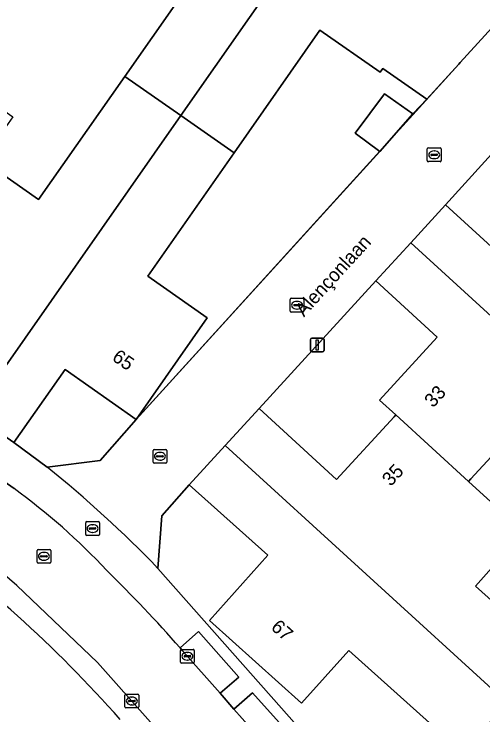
# Model space of a CAD drawing. Extents: x 158472 to 159562, y 388525 to 389606.
# Drawn here: x 158728.1 to 158762.2, y 389083.9 to 389134.9 of the extents above; entities that cross this region are included whole.
import ezdxf

# ---------------------------------------------------------------- set-up
doc = ezdxf.new("R2010")
doc.units = 0
for name, color, linetype in [('IMGEO_Brandkraan', 7, 'Continuous'), ('IMGEO_Erf', 7, 'Continuous'), ('IMGEO_Kolk', 7, 'Continuous'), ('IMGEO_Lichtmast', 7, 'Continuous'), ('IMGEO_Muur', 7, 'Continuous'), ('IMGEO_Openbare_ruimte_label', 7, 'Continuous'), ('IMGEO_Pand', 7, 'Continuous'), ('IMGEO_Pand_nummerreeks', 7, 'Continuous'), ('IMGEO_Parkeervlak_open', 7, 'Continuous'), ('IMGEO_Rijbaan_lokaal_open', 7, 'Continuous'), ('IMGEO_Rioolput', 7, 'Continuous'), ('IMGEO_Voetpad_open', 7, 'Continuous')]:
    doc.layers.add(name, color=color, linetype=linetype)

msp = doc.modelspace()

# ---------------------------------------------------------------- linework, layer by layer
at = {"layer": 'IMGEO_Brandkraan'}
for p, q in [((158733.348, 389097.923), (158734.2, 389097.923)), ((158733.273, 389096.997), (158733.273, 389097.849)), ((158733.532, 389097.417), (158733.532, 389097.429)), ((158733.575, 389097.466), (158733.973, 389097.466)), ((158733.761, 389097.703), (158733.786, 389097.703)), ((158734.016, 389097.429), (158734.016, 389097.417)), ((158734.274, 389097.849), (158734.274, 389096.997)), ((158734.2, 389096.923), (158733.348, 389096.923)), ((158733.97, 389097.38), (158733.572, 389097.38)), ((158733.784, 389097.143), (158733.759, 389097.143))]:
    msp.add_line(p, q, dxfattribs=at)
for points in [[(158733.348, 389097.923), (158734.2, 389097.923)], [(158733.273, 389096.997), (158733.273, 389097.849)], [(158734.274, 389097.849), (158734.274, 389096.997)], [(158734.2, 389096.923), (158733.348, 389096.923)]]:
    msp.add_lwpolyline(points, dxfattribs=at)
for centre, radius, start, end in [((158733.35, 389097.847), 0.0765, 91.552, 178.448), ((158733.35, 389097.847), 0.0765, 91.552, 178.448), ((158734.198, 389097.847), 0.0765, 1.552, 88.448), ((158734.198, 389097.847), 0.0765, 1.552, 88.448), ((158733.572, 389097.426), 0.0403, 85.8775, 175.7526), ((158733.569, 389097.416), 0.0366, 178.938, 274.7102), ((158733.973, 389097.423), 0.043, 264.8664, 352.4533), ((158733.977, 389097.428), 0.0386, 1.7309, 96.639), ((158733.35, 389096.999), 0.0765, 181.552, 268.448), ((158733.35, 389096.999), 0.0765, 181.552, 268.448), ((158734.198, 389096.999), 0.0765, 271.552, 358.448), ((158734.198, 389096.999), 0.0765, 271.552, 358.448)]:
    msp.add_arc(centre, radius, start, end, dxfattribs=at)
for centre, major_axis, ratio, start_param, end_param in [((158733.76, 389097.423), (-0.387, 0.002), 0.722429, 4.712389, 7.853982), ((158733.785, 389097.423), (-0.39, 0.002), 0.717154, 1.570796, 4.712389)]:
    msp.add_ellipse(centre, major_axis=major_axis, ratio=ratio, start_param=start_param, end_param=end_param, dxfattribs=at)
at = {"layer": 'IMGEO_Erf'}
for points in [[(158742.26, 389139.1), (158738.236, 389141.914), (158737.74, 389141.205), (158737.633, 389141.28), (158733.367, 389144.264), (158727.701, 389136.164), (158723.669, 389130.4), (158727.969, 389127.391), (158725.737, 389124.229), (158729.847, 389121.355), (158736.122, 389130.326)], [(158754.672, 389124.87), (158752.887, 389126.194), (158755.009, 389129.056), (158757.083, 389127.604), (158758.098, 389128.664), (158754.895, 389130.904), (158754.704, 389130.631), (158750.32, 389133.698), (158744.071, 389124.764), (158737.786, 389115.78), (158742.118, 389112.75), (158736.952, 389105.364)], [(158759.468, 389120.986), (158763.907, 389116.916), (158768.139, 389121.531), (158772.285, 389126.053), (158767.797, 389130.168)], [(158754.39, 389115.448), (158745.896, 389106.148), (158751.528, 389100.984), (158755.715, 389105.55), (158755.841, 389105.687), (158754.657, 389106.768), (158758.859, 389111.351)], [(158730.482, 389101.889), (158734.321, 389102.376), (158736.952, 389105.364), (158731.769, 389108.989), (158728.054, 389103.678)]]:
    msp.add_lwpolyline(points, close=True, dxfattribs=at)
for points in [[(158764.551, 389104.563), (158761.309, 389101.027), (158761.143, 389100.845), (158765.168, 389097.17), (158761.633, 389093.23), (158767.137, 389088.293)], [(158763.955, 389084.746), (158760.701, 389081.12), (158757.9, 389078.962), (158756.592, 389080.289), (158758.992, 389082.653), (158752.414, 389088.553), (158748.973, 389084.717), (158742.277, 389090.723), (158746.537, 389095.473), (158740.815, 389100.606), (158738.808, 389098.335), (158738.53, 389094.525), (158748.078, 389083.72), (158754.435, 389076.526), (158771.254, 389057.492)]]:
    msp.add_lwpolyline(points, dxfattribs=at)
msp.add_arc((158667.256, 389023.192), 91.299, 41.36595, 54.6966, dxfattribs=at)
at = {"layer": 'IMGEO_Kolk'}
for p, q in [((158758.135, 389124.194), (158758.135, 389125.046)), ((158758.21, 389125.12), (158759.062, 389125.12)), ((158759.136, 389125.046), (158759.136, 389124.194)), ((158758.394, 389124.614), (158758.394, 389124.626)), ((158758.832, 389124.577), (158758.434, 389124.577)), ((158758.437, 389124.663), (158758.835, 389124.663)), ((158758.623, 389124.9), (158758.648, 389124.9)), ((158758.878, 389124.626), (158758.878, 389124.614)), ((158759.062, 389124.12), (158758.21, 389124.12)), ((158758.646, 389124.34), (158758.621, 389124.34)), ((158748.155, 389113.249), (158748.155, 389114.101)), ((158748.23, 389114.175), (158749.082, 389114.175)), ((158748.457, 389113.718), (158748.855, 389113.718)), ((158748.643, 389113.955), (158748.668, 389113.955)), ((158749.156, 389114.101), (158749.156, 389113.249)), ((158748.414, 389113.669), (158748.414, 389113.681)), ((158748.852, 389113.632), (158748.454, 389113.632)), ((158748.666, 389113.395), (158748.641, 389113.395)), ((158748.898, 389113.681), (158748.898, 389113.669)), ((158749.082, 389113.175), (158748.23, 389113.175)), ((158738.175, 389102.254), (158738.175, 389103.106)), ((158738.25, 389103.18), (158739.102, 389103.18)), ((158739.176, 389103.106), (158739.176, 389102.254)), ((158738.434, 389102.674), (158738.434, 389102.686)), ((158738.872, 389102.637), (158738.474, 389102.637)), ((158738.477, 389102.723), (158738.875, 389102.723)), ((158738.663, 389102.96), (158738.688, 389102.96)), ((158738.918, 389102.686), (158738.918, 389102.674)), ((158739.102, 389102.18), (158738.25, 389102.18)), ((158738.686, 389102.4), (158738.661, 389102.4)), ((158740.177, 389087.703), (158740.177, 389088.555)), ((158740.252, 389088.629), (158741.104, 389088.629)), ((158740.665, 389088.409), (158740.69, 389088.409)), ((158741.178, 389088.555), (158741.178, 389087.703)), ((158740.436, 389088.123), (158740.436, 389088.135)), ((158740.874, 389088.086), (158740.476, 389088.086)), ((158740.479, 389088.172), (158740.877, 389088.172)), ((158740.688, 389087.849), (158740.663, 389087.849)), ((158740.92, 389088.135), (158740.92, 389088.123)), ((158741.104, 389087.629), (158740.252, 389087.629)), ((158736.131, 389084.445), (158736.131, 389085.297)), ((158736.206, 389085.371), (158737.058, 389085.371)), ((158736.619, 389085.151), (158736.644, 389085.151)), ((158737.132, 389085.297), (158737.132, 389084.445)), ((158736.39, 389084.865), (158736.39, 389084.877)), ((158736.828, 389084.828), (158736.43, 389084.828)), ((158736.433, 389084.914), (158736.831, 389084.914)), ((158736.874, 389084.877), (158736.874, 389084.865)), ((158737.058, 389084.371), (158736.206, 389084.371)), ((158736.642, 389084.591), (158736.617, 389084.591))]:
    msp.add_line(p, q, dxfattribs=at)
for points in [[(158758.135, 389124.194), (158758.135, 389125.046)], [(158758.21, 389125.12), (158759.062, 389125.12)], [(158759.136, 389125.046), (158759.136, 389124.194)], [(158759.062, 389124.12), (158758.21, 389124.12)], [(158748.155, 389113.249), (158748.155, 389114.101)], [(158748.23, 389114.175), (158749.082, 389114.175)], [(158749.156, 389114.101), (158749.156, 389113.249)], [(158749.082, 389113.175), (158748.23, 389113.175)], [(158738.175, 389102.254), (158738.175, 389103.106)], [(158738.25, 389103.18), (158739.102, 389103.18)], [(158739.176, 389103.106), (158739.176, 389102.254)], [(158739.102, 389102.18), (158738.25, 389102.18)], [(158740.177, 389087.703), (158740.177, 389088.555)], [(158740.252, 389088.629), (158741.104, 389088.629)], [(158741.178, 389088.555), (158741.178, 389087.703)], [(158741.104, 389087.629), (158740.252, 389087.629)], [(158736.131, 389084.445), (158736.131, 389085.297)], [(158736.206, 389085.371), (158737.058, 389085.371)], [(158737.132, 389085.297), (158737.132, 389084.445)], [(158737.058, 389084.371), (158736.206, 389084.371)]]:
    msp.add_lwpolyline(points, dxfattribs=at)
for centre, radius, start, end in [((158758.212, 389125.044), 0.0765, 91.552, 178.448), ((158758.212, 389125.044), 0.0765, 91.552, 178.448), ((158759.06, 389125.044), 0.0765, 1.552, 88.448), ((158759.06, 389125.044), 0.0765, 1.552, 88.448), ((158758.434, 389124.623), 0.0403, 85.8775, 175.7526), ((158758.431, 389124.613), 0.0366, 178.938, 274.7102), ((158758.835, 389124.62), 0.043, 264.8664, 352.4533), ((158758.839, 389124.625), 0.0386, 1.7309, 96.639), ((158758.212, 389124.196), 0.0765, 181.552, 268.448), ((158758.212, 389124.196), 0.0765, 181.552, 268.448), ((158759.06, 389124.196), 0.0765, 271.552, 358.448), ((158759.06, 389124.196), 0.0765, 271.552, 358.448), ((158748.232, 389114.099), 0.0765, 91.552, 178.448), ((158748.232, 389114.099), 0.0765, 91.552, 178.448), ((158748.454, 389113.678), 0.0403, 85.8775, 175.7526), ((158748.859, 389113.68), 0.0386, 1.7309, 96.639), ((158749.08, 389114.099), 0.0765, 1.552, 88.448), ((158749.08, 389114.099), 0.0765, 1.552, 88.448), ((158748.232, 389113.251), 0.0765, 181.552, 268.448), ((158748.232, 389113.251), 0.0765, 181.552, 268.448), ((158748.451, 389113.668), 0.0366, 178.938, 274.7102), ((158748.855, 389113.675), 0.043, 264.8664, 352.4533), ((158749.08, 389113.251), 0.0765, 271.552, 358.448), ((158749.08, 389113.251), 0.0765, 271.552, 358.448), ((158738.252, 389103.104), 0.0765, 91.552, 178.448), ((158738.252, 389103.104), 0.0765, 91.552, 178.448), ((158739.1, 389103.104), 0.0765, 1.552, 88.448), ((158739.1, 389103.104), 0.0765, 1.552, 88.448), ((158738.474, 389102.683), 0.0403, 85.8775, 175.7526), ((158738.471, 389102.673), 0.0366, 178.938, 274.7102), ((158738.875, 389102.68), 0.043, 264.8664, 352.4533), ((158738.879, 389102.685), 0.0386, 1.7309, 96.639), ((158738.252, 389102.256), 0.0765, 181.552, 268.448), ((158738.252, 389102.256), 0.0765, 181.552, 268.448), ((158739.1, 389102.256), 0.0765, 271.552, 358.448), ((158739.1, 389102.256), 0.0765, 271.552, 358.448), ((158740.254, 389088.553), 0.0765, 91.552, 178.448), ((158740.254, 389088.553), 0.0765, 91.552, 178.448), ((158741.102, 389088.553), 0.0765, 1.552, 88.448), ((158741.102, 389088.553), 0.0765, 1.552, 88.448), ((158740.254, 389087.705), 0.0765, 181.552, 268.448), ((158740.254, 389087.705), 0.0765, 181.552, 268.448), ((158740.476, 389088.132), 0.0403, 85.8775, 175.7526), ((158740.473, 389088.122), 0.0366, 178.938, 274.7102), ((158740.877, 389088.129), 0.043, 264.8664, 352.4533), ((158740.881, 389088.134), 0.0386, 1.7309, 96.639), ((158741.102, 389087.705), 0.0765, 271.552, 358.448), ((158741.102, 389087.705), 0.0765, 271.552, 358.448), ((158736.208, 389085.295), 0.0765, 91.552, 178.448), ((158736.208, 389085.295), 0.0765, 91.552, 178.448), ((158737.056, 389085.295), 0.0765, 1.552, 88.448), ((158737.056, 389085.295), 0.0765, 1.552, 88.448), ((158736.43, 389084.874), 0.0403, 85.8775, 175.7526), ((158736.427, 389084.864), 0.0366, 178.938, 274.7102), ((158736.831, 389084.871), 0.043, 264.8664, 352.4533), ((158736.835, 389084.876), 0.0386, 1.7309, 96.639), ((158736.208, 389084.447), 0.0765, 181.552, 268.448), ((158736.208, 389084.447), 0.0765, 181.552, 268.448), ((158737.056, 389084.447), 0.0765, 271.552, 358.448), ((158737.056, 389084.447), 0.0765, 271.552, 358.448)]:
    msp.add_arc(centre, radius, start, end, dxfattribs=at)
for centre, major_axis, ratio, start_param, end_param in [((158758.622, 389124.62), (-0.387, 0.002), 0.722429, 4.712389, 7.853982), ((158758.647, 389124.62), (-0.39, 0.002), 0.717154, 1.570796, 4.712389), ((158748.642, 389113.675), (-0.387, 0.002), 0.722429, 4.712389, 7.853982), ((158748.667, 389113.675), (-0.39, 0.002), 0.717154, 1.570796, 4.712389), ((158738.662, 389102.68), (-0.387, 0.002), 0.722429, 4.712389, 7.853982), ((158738.687, 389102.68), (-0.39, 0.002), 0.717154, 1.570796, 4.712389), ((158740.664, 389088.129), (-0.387, 0.002), 0.722429, 4.712389, 7.853982), ((158740.689, 389088.129), (-0.39, 0.002), 0.717154, 1.570796, 4.712389), ((158736.618, 389084.871), (-0.387, 0.002), 0.722429, 4.712389, 7.853982), ((158736.643, 389084.871), (-0.39, 0.002), 0.717154, 1.570796, 4.712389)]:
    msp.add_ellipse(centre, major_axis=major_axis, ratio=ratio, start_param=start_param, end_param=end_param, dxfattribs=at)
at = {"layer": 'IMGEO_Lichtmast'}
for p, q in [((158749.628, 389110.381), (158749.628, 389111.181)), ((158749.628, 389111.181), (158749.628, 389110.381)), ((158749.728, 389111.281), (158750.518, 389111.281)), ((158750.518, 389111.281), (158749.728, 389111.281)), ((158750.618, 389111.181), (158750.618, 389110.381)), ((158750.618, 389110.381), (158750.618, 389111.181)), ((158750.518, 389110.281), (158749.728, 389110.281)), ((158749.728, 389110.281), (158750.518, 389110.281))]:
    msp.add_line(p, q, dxfattribs=at)
msp.add_lwpolyline([(158750.048, 389111.156), (158750.198, 389111.156), (158750.198, 389110.406), (158750.048, 389110.406), (158750.048, 389111.156)], dxfattribs=at)
for centre, start, end in [((158749.728, 389111.181), 90, 180), ((158749.728, 389111.181), 90, 180), ((158750.518, 389111.181), 0, 90), ((158750.518, 389111.181), 360, 90), ((158749.728, 389110.381), 180, 270), ((158749.728, 389110.381), 180, 270), ((158750.518, 389110.381), 270, 0), ((158750.518, 389110.381), 270, 0)]:
    msp.add_arc(centre, 0.1, start, end, dxfattribs=at)
at = {"layer": 'IMGEO_Muur'}
msp.add_lwpolyline([(158736.952, 389105.364), (158760.421, 389131.219)], dxfattribs=at)
at = {"layer": 'IMGEO_Pand'}
for points in [[(158755.371, 389149.144), (158752.415, 389151.212), (158752.23, 389151.341), (158748.467, 389145.96), (158743.413, 389149.495), (158742.779, 389148.593), (158737.633, 389141.28), (158737.74, 389141.205), (158738.236, 389141.914), (158742.26, 389139.1), (158736.122, 389130.326), (158740.19, 389127.47)], [(158767.367, 389141.09), (158764.701, 389142.954), (158761.989, 389139.077), (158760.835, 389137.427), (158754.708, 389141.713), (158758.416, 389147.014), (158755.371, 389149.144), (158740.19, 389127.47), (158744.071, 389124.764), (158750.32, 389133.698), (158754.704, 389130.631), (158754.895, 389130.904), (158758.098, 389128.664), (158760.421, 389131.219), (158760.536, 389131.345), (158765.398, 389136.693), (158767.718, 389139.244)], [(158740.19, 389127.47), (158736.122, 389130.326), (158729.847, 389121.355), (158725.737, 389124.229), (158720.542, 389116.869), (158725.605, 389113.327), (158721.878, 389107.998), (158725.014, 389105.804)], [(158757.083, 389127.604), (158755.009, 389129.056), (158752.887, 389126.194), (158754.672, 389124.87)], [(158740.19, 389127.47), (158725.014, 389105.804), (158728.054, 389103.678), (158731.769, 389108.989), (158736.952, 389105.364), (158742.118, 389112.75), (158737.786, 389115.78), (158744.071, 389124.764)], [(158768.139, 389121.531), (158763.907, 389116.916), (158759.468, 389120.986), (158756.926, 389118.214), (158775.345, 389101.412), (158778.5, 389104.854), (158770.989, 389111.741), (158774.578, 389115.654)], [(158756.926, 389118.214), (158754.39, 389115.448), (158758.859, 389111.351), (158754.657, 389106.768), (158755.841, 389105.687), (158761.143, 389100.845), (158761.309, 389101.027), (158764.551, 389104.563), (158771.984, 389097.747), (158774.489, 389100.479), (158775.345, 389101.412)], [(158761.143, 389100.845), (158755.841, 389105.687), (158755.715, 389105.55), (158751.528, 389100.984), (158745.896, 389106.148), (158743.43, 389103.458), (158763.955, 389084.746), (158764.041, 389084.842), (158767.137, 389088.293), (158761.633, 389093.23), (158765.168, 389097.17)], [(158743.43, 389103.458), (158740.815, 389100.606), (158746.537, 389095.473), (158742.277, 389090.723), (158748.973, 389084.717), (158752.414, 389088.553), (158758.992, 389082.653), (158760.701, 389081.12), (158763.955, 389084.746)]]:
    msp.add_lwpolyline(points, close=True, dxfattribs=at)
at = {"layer": 'IMGEO_Parkeervlak_open'}
for points in [[(158743.055, 389085.433), (158744.417, 389086.607), (158741.494, 389089.937), (158740.139, 389088.752), (158740.324, 389088.534)], [(158744.053, 389084.282), (158747.079, 389080.887), (158748.436, 389082.084), (158745.419, 389085.472)]]:
    msp.add_lwpolyline(points, close=True, dxfattribs=at)
at = {"layer": 'IMGEO_Rijbaan_lokaal_open'}
for points in [[(158738.53, 389094.525), (158738.808, 389098.335), (158740.815, 389100.606), (158743.43, 389103.458), (158745.896, 389106.148), (158754.39, 389115.448), (158756.926, 389118.214), (158759.468, 389120.986), (158767.797, 389130.168), (158770.397, 389133.003), (158772.904, 389135.737), (158777.199, 389140.49)], [(158765.398, 389136.693), (158760.536, 389131.345), (158760.421, 389131.219), (158758.098, 389128.664), (158757.083, 389127.604), (158754.672, 389124.87), (158736.952, 389105.364), (158734.321, 389102.376), (158730.482, 389101.889)], [(158728.059, 389100.327), (158719.346, 389106.437), (158717.316, 389107.86), (158714.375, 389103.662), (158719.28, 389100.228)], [(158728.269, 389093.269), (158734.13, 389087.685), (158750.89, 389068.801), (158754.77, 389072.24), (158752.049, 389075.317), (158751.04, 389076.423), (158748.117, 389079.762), (158747.079, 389080.887), (158744.053, 389084.282), (158743.055, 389085.433), (158740.324, 389088.534), (158740.139, 389088.752)], [(158752.708, 389066.752), (158750.89, 389068.801), (158734.13, 389087.685), (158728.269, 389093.269)]]:
    msp.add_lwpolyline(points, dxfattribs=at)
for centre, radius, start, end in [((158675.445, 389033.66), 87.66, 43.97385, 51.1085), ((158656.143, 389009.389), 110.626, 49.30893, 55.19926), ((158656.143, 389009.389), 110.626, 49.30893, 55.19926), ((158699.795, 389061.446), 48.069, 43.24, 53.9845), ((158667.256, 389023.192), 91.299, 41.36595, 54.6966), ((158654.271, 389012.754), 114.669, 41.51082, 45.38213)]:
    msp.add_arc(centre, radius, start, end, dxfattribs=at)
at = {"layer": 'IMGEO_Rioolput'}
for p, q in [((158729.808, 389095.901), (158730.66, 389095.901)), ((158729.733, 389094.975), (158729.733, 389095.827)), ((158729.992, 389095.395), (158729.992, 389095.407)), ((158730.43, 389095.358), (158730.032, 389095.358)), ((158730.035, 389095.444), (158730.433, 389095.444)), ((158730.221, 389095.681), (158730.246, 389095.681)), ((158730.476, 389095.407), (158730.476, 389095.395)), ((158730.734, 389095.827), (158730.734, 389094.975)), ((158730.66, 389094.901), (158729.808, 389094.901)), ((158730.244, 389095.121), (158730.219, 389095.121))]:
    msp.add_line(p, q, dxfattribs=at)
for points in [[(158729.808, 389095.901), (158730.66, 389095.901)], [(158729.733, 389094.975), (158729.733, 389095.827)], [(158730.734, 389095.827), (158730.734, 389094.975)], [(158730.66, 389094.901), (158729.808, 389094.901)]]:
    msp.add_lwpolyline(points, dxfattribs=at)
for centre, radius, start, end in [((158729.81, 389095.825), 0.0765, 91.552, 178.448), ((158729.81, 389095.825), 0.0765, 91.552, 178.448), ((158730.658, 389095.825), 0.0765, 1.552, 88.448), ((158730.658, 389095.825), 0.0765, 1.552, 88.448), ((158730.032, 389095.404), 0.0403, 85.8775, 175.7526), ((158730.029, 389095.394), 0.0366, 178.938, 274.7102), ((158730.433, 389095.401), 0.043, 264.8664, 352.4533), ((158730.437, 389095.406), 0.0386, 1.7309, 96.639), ((158729.81, 389094.977), 0.0765, 181.552, 268.448), ((158729.81, 389094.977), 0.0765, 181.552, 268.448), ((158730.658, 389094.977), 0.0765, 271.552, 358.448), ((158730.658, 389094.977), 0.0765, 271.552, 358.448)]:
    msp.add_arc(centre, radius, start, end, dxfattribs=at)
for centre, major_axis, ratio, start_param, end_param in [((158730.22, 389095.401), (-0.387, 0.002), 0.722429, 4.712389, 7.853982), ((158730.245, 389095.401), (-0.39, 0.002), 0.717154, 1.570796, 4.712389)]:
    msp.add_ellipse(centre, major_axis=major_axis, ratio=ratio, start_param=start_param, end_param=end_param, dxfattribs=at)
at = {"layer": 'IMGEO_Voetpad_open'}
for points in [[(158730.482, 389101.889), (158728.054, 389103.678), (158725.014, 389105.804), (158721.878, 389107.998), (158711.658, 389115.172), (158708.635, 389117.286), (158705.497, 389119.481), (158695.221, 389126.57), (158692.205, 389128.68), (158689.021, 389130.907), (158678.87, 389138.048), (158672.706, 389142.361)], [(158698.044, 389121.368), (158699.282, 389120.506), (158700.258, 389122.013), (158704.038, 389119.361), (158703.009, 389117.912), (158710.878, 389112.337), (158711.904, 389113.831), (158715.578, 389111.196), (158714.59, 389109.772), (158715.048, 389109.451), (158715.809, 389108.917), (158716.836, 389110.382), (158720.374, 389107.904), (158719.346, 389106.437), (158728.059, 389100.327)], [(158765.739, 389048.631), (158767.187, 389047.566), (158767.926, 389046.996), (158771.254, 389057.492), (158754.435, 389076.526), (158748.078, 389083.72), (158738.53, 389094.525)], [(158740.139, 389088.752), (158741.494, 389089.937), (158744.417, 389086.607), (158743.055, 389085.433), (158744.053, 389084.282), (158745.419, 389085.472), (158748.436, 389082.084), (158747.079, 389080.887), (158748.117, 389079.762), (158749.438, 389080.948), (158752.399, 389077.622), (158751.04, 389076.423), (158752.049, 389075.317), (158753.403, 389076.488), (158756.491, 389072.972), (158755.129, 389071.833), (158756.587, 389070.188), (158762.444, 389063.578), (158763.774, 389064.75), (158766.739, 389061.32), (158765.424, 389060.214)]]:
    msp.add_lwpolyline(points, dxfattribs=at)
for centre, radius, start, end in [((158675.445, 389033.66), 87.66, 43.97385, 51.1085), ((158699.795, 389061.446), 48.069, 43.24, 53.9845), ((158654.271, 389012.754), 114.669, 41.51082, 45.38213)]:
    msp.add_arc(centre, radius, start, end, dxfattribs=at)

# ---------------------------------------------------------------- texts
at = {"layer": 'IMGEO_Openbare_ruimte_label'}
msp.add_text('Alençonlaan', height=1, rotation=47.6338, dxfattribs=at).set_placement((158749.155, 389112.775))
at = {"layer": 'IMGEO_Pand_nummerreeks'}
for s, rotation, p in [('65', 325.031, (158735.128, 389109.715)), ('33', 47.481, (158758.555, 389106.168)), ('35', 47.481, (158755.48, 389100.442)), ('67', 318.1111, (158746.692, 389090.148))]:
    msp.add_text(s, height=1, rotation=rotation, dxfattribs=at).set_placement(p)

doc.saveas('drawing.dxf')
